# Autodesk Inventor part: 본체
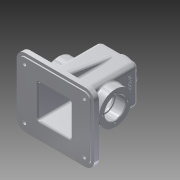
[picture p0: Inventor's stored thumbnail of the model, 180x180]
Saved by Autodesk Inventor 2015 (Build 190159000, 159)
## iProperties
Created: 2016-02
Part Number: 본체
Material: 알루미늄 6061
Document SubType Name: Modeling
Designer: Administrator
Density: 2.7 g/cm^3
Appearance: 알루미늄 - 평지
Mass: 797.447 g
Surface Area: 911.36 cm^2
Volume: 295.351 cm^3
Author: Administrator
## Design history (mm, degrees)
sketch "스케치1"
  geometry: L1 (65, 57.5)-(-65, 57.5); L2 (-65, 57.5)-(-65, -57.5); L3 (-65, -57.5)-(65, -57.5); L4 (65, -57.5)-(65, 57.5); L5 (65, 57.5)-(-65, -57.5); L6 (-65, 57.5)-(65, -57.5); 1 further point
  constraints: 12 end point, 2 midpoint, 2 parallel, 1 horizontal, 1 perpendicular
  dimensions: "d0" = 130 distance of L2.end L3.end; "d1" = 115 distance of L1.end L2.end
extrude "돌출1" new body sketch "스케치1" distance "d2" = 8; taper "d3" = 0 deg
sketch "스케치2"
  geometry: L1 (-60, 52.5)-(60, 52.5); L2 (60, 52.5)-(60, -52.5); L3 (60, -52.5)-(-60, -52.5); L4 (-60, -52.5)-(-60, 52.5); L5 (-60, 52.5)-(60, -52.5); L6 (60, 52.5)-(-60, -52.5); 1 further point
  constraints: 12 end point, 2 midpoint, 2 parallel, 1 horizontal, 1 perpendicular
  dimensions: "d4" = 120 distance of L2.end L3.end; "d5" = 105 distance of L1.end L2.end
extrude "돌출2" join sketch "스케치2" distance "d6" = 2; taper "d7" = 0 deg
sketch "스케치3"
  geometry: L1 (-65, -57.5)-(-65, 57.5) reference; L2 (-65, 57.5)-(65, 57.5) reference; L3 (65, 57.5)-(65, -57.5) reference; L4 (65, -57.5)-(-65, -57.5) reference; L5 (-32.5, -32.5)-(32.5, -32.5); L6 (32.5, -32.5)-(32.5, 32.5); L7 (32.5, 32.5)-(-32.5, 32.5); L8 (-32.5, 32.5)-(-32.5, -32.5); L9 (-32.5, -32.5)-(32.5, 32.5); L10 (32.5, -32.5)-(-32.5, 32.5); 1 further point
  constraints: 12 end point, 2 midpoint, 2 parallel, 1 horizontal, 1 perpendicular
  dimensions: "d8" = 65 distance of L6.end L7.end; "d9" = 65 distance of L5.end L6.end
extrude "돌출3" join sketch "스케치3" distance "d10" = 100; taper "d11" = 0 deg
sketch "스케치4"
  geometry: L1 (90, 0)-(90, -8) reference; L2 (90, -8)-(85, -8) reference; L3 (85, -8)-(85, -10) reference; L4 (85, -10)-(-20, -10) reference; L5 (-20, -10)-(-20, -8) reference; L6 (-20, -8)-(-25, -8) reference; L7 (-25, -8)-(-25, 0) reference; L8 (-25, 0)-(0, 0) reference; L9 (0, 0)-(65, 0) reference; L10 (65, 0)-(90, 0) reference; L11 (0, 0)-(0, 100) reference; L12 (0, 100)-(65, 100) reference; L13 (65, 100)-(65, 0) reference; L14 (-45.844, 45)-(144.35, 45); L15 (32.5, -8)-(32.5, 115.306); C1 r 27.5 at (32.5, 45)
  constraints: 4 end point, 2 point on line, 1 centre point, 1 horizontal, 1 vertical
  dimensions: "d12" = 55 distance between parallel lines of L4 L14; "d13" = 55 diameter of C1
extrude "돌출4" join sketch "스케치4" distance "d14" = 15; taper "d15" = 0 deg
sketch "스케치5"
  geometry: L1 (-25, -8)-(-25, 0) reference; L2 (-25, 0)-(0, 0) reference; L3 (0, 0)-(0, 100) reference; L4 (0, 100)-(65, 100) reference; L5 (65, 100)-(65, 0) reference; L6 (65, 0)-(90, 0) reference; L7 (90, 0)-(90, -8) reference; L8 (90, -8)-(85, -8) reference; L9 (85, -8)-(85, -10) reference; L10 (85, -10)-(-20, -10) reference; L11 (-20, -10)-(-20, -8) reference; L12 (-20, -8)-(-25, -8) reference; L13 (0, 0)-(65, 0) reference; L14 (-28.845, 45)-(133.756, 45); L15 (32.5, -8)-(32.5, 125.406); C1 r 27.5 at (32.5, 45)
  constraints: 4 end point, 2 point on line, 1 centre point, 1 horizontal, 1 vertical
  dimensions: "d16" = 55 distance between parallel lines of L10 L14; "d17" = 55 diameter of C1
extrude "돌출5" join sketch "스케치5" distance "d18" = 15; taper "d19" = 0 deg
sketch "스케치6"
  geometry: L1 (-32.5, -32.5)-(-32.5, 32.5) reference; L2 (-32.5, 32.5)-(32.5, 32.5) reference; L3 (32.5, 32.5)-(32.5, -32.5) reference; L4 (32.5, -32.5)-(-32.5, -32.5) reference; C1 r 20 at (0, 0); 1 further point
  constraints: 1 centre point, 1 coincident
  dimensions: "d21" = 40 diameter of C1
extrude "돌출6" join sketch "스케치6" distance "d22" = 10; taper "d23" = 0 deg
sketch "스케치7"
  geometry: C1 r 20 at (0, 0) reference; C2 r 10.5 at (0, 0); 1 further point
  constraints: 1 centre point, 1 coincident
  dimensions: "d24" = 21 diameter of C2
extrude "돌출7" cut sketch "스케치7" distance "d25" = 500; taper "d26" = 0 deg
sketch "스케치8" dims "d27" = 29
  geometry: C1 r 10.5 at (0, 0) reference; C2 r 20 at (0, 0) reference; 3 further points
  constraints: 2 vertical alignment, 1 coincident, 2 other
hole "구멍1" sketch "스케치8" at (0, 14.5) diameter "d28" = 2.459; stored, may be unused: countersink angle "d32" = 90 deg, drill point angle "d34" = 118 deg; dims "d29" = 7, "d30" = 4, "d31" = 2, "d33" = 9
sketch "스케치9"
  geometry: L1 (-27.5, -27.5)-(27.5, -27.5); L2 (27.5, -27.5)-(27.5, 27.5); L3 (27.5, 27.5)-(-27.5, 27.5); L4 (-27.5, 27.5)-(-27.5, -27.5); L5 (-27.5, -27.5)-(27.5, 27.5); L6 (27.5, -27.5)-(-27.5, 27.5); 1 further point
  constraints: 12 end point, 2 midpoint, 2 parallel, 1 horizontal, 1 perpendicular
  dimensions: "d38" = 55 distance of L2.end L3.end; "d39" = 55 distance of L1.end L2.end
extrude "돌출8" cut sketch "스케치9" distance "d40" = 105; taper "d41" = 0 deg
sketch "스케치10"
  geometry: L1 (57.5, -45)-(57.5, -53) reference; L2 (57.5, -53)-(52.5, -53) reference; L3 (52.5, -53)-(52.5, -55) reference; L4 (52.5, -55)-(-52.5, -55) reference; L5 (-52.5, -55)-(-52.5, -53) reference; L6 (-52.5, -53)-(-57.5, -53) reference; L7 (-57.5, -53)-(-57.5, -45) reference; L8 (-57.5, -45)-(57.5, -45) reference; C1 r 27.5 at (0, 0) reference; C2 r 17.5 at (0, 0); 1 further point
  constraints: 1 centre point, 1 coincident
  dimensions: "d42" = 35 diameter of C2
extrude "돌출9" cut sketch "스케치10" distance "d43" = 17; taper "d44" = 0 deg
sketch "스케치11"
  geometry: L1 (57.5, -45)-(57.5, -53) reference; L2 (57.5, -53)-(52.5, -53) reference; L3 (52.5, -53)-(52.5, -55) reference; L4 (52.5, -55)-(-52.5, -55) reference; L5 (-52.5, -55)-(-52.5, -53) reference; L6 (-52.5, -53)-(-57.5, -53) reference; L7 (-57.5, -53)-(-57.5, -45) reference; L8 (-57.5, -45)-(-32.5, -45) reference; L9 (-32.5, -45)-(-32.5, 55) reference; L10 (-32.5, 55)-(32.5, 55) reference; L11 (32.5, 55)-(32.5, -45) reference; L12 (32.5, -45)-(57.5, -45) reference; C1 r 17.5 at (0, 0) reference; C2 r 15 at (0, 0); 1 further point
  constraints: 1 centre point, 1 coincident
  dimensions: "d45" = 30 diameter of C2
extrude "돌출10" cut sketch "스케치11" distance "d46" = 3; taper "d47" = 0 deg
sketch "스케치12"
  geometry: L1 (-57.5, -53)-(-57.5, -45) reference; L2 (-57.5, -45)-(57.5, -45) reference; L3 (57.5, -45)-(57.5, -53) reference; L4 (57.5, -53)-(52.5, -53) reference; L5 (52.5, -53)-(52.5, -55) reference; L6 (52.5, -55)-(-52.5, -55) reference; L7 (-52.5, -55)-(-52.5, -53) reference; L8 (-52.5, -53)-(-57.5, -53) reference; C1 r 27.5 at (0, 0) reference; C2 r 17.5 at (0, 0); 1 further point
  constraints: 1 centre point, 1 coincident
  dimensions: "d48" = 35 diameter of C2
extrude "돌출11" cut sketch "스케치12" distance "d49" = 17; taper "d50" = 0 deg
sketch "스케치13"
  geometry: L1 (-57.5, -53)-(-57.5, -45) reference; L2 (-57.5, -45)-(-32.5, -45) reference; L3 (-32.5, -45)-(-32.5, 55) reference; L4 (-32.5, 55)-(32.5, 55) reference; L5 (32.5, 55)-(32.5, -45) reference; L6 (32.5, -45)-(57.5, -45) reference; L7 (57.5, -45)-(57.5, -53) reference; L8 (57.5, -53)-(52.5, -53) reference; L9 (52.5, -53)-(52.5, -55) reference; L10 (52.5, -55)-(-52.5, -55) reference; L11 (-52.5, -55)-(-52.5, -53) reference; L12 (-52.5, -53)-(-57.5, -53) reference; C1 r 17.5 at (0, 0) reference; C2 r 15 at (0, 0); 1 further point
  constraints: 1 centre point, 1 coincident
  dimensions: "d51" = 30 diameter of C2
extrude "돌출12" cut sketch "스케치13" distance "d52" = 3; taper "d53" = 0 deg
sketch "스케치14" dims "d54" = 42
  geometry: L1 (-57.5, -53)-(-57.5, -45) reference; L2 (-57.5, -45)-(57.5, -45) reference; L3 (57.5, -45)-(57.5, -53) reference; L4 (57.5, -53)-(52.5, -53) reference; L5 (52.5, -53)-(52.5, -55) reference; L6 (52.5, -55)-(-52.5, -55) reference; L7 (-52.5, -55)-(-52.5, -53) reference; L8 (-52.5, -53)-(-57.5, -53) reference; C1 r 17.5 at (0, 0) reference; C2 r 27.5 at (0, 0) reference; 3 further points
  constraints: 2 vertical alignment, 1 coincident, 2 other
hole "구멍2" sketch "스케치14" at (0, 21) diameter "d55" = 3.242; stored, may be unused: countersink angle "d59" = 90 deg, drill point angle "d61" = 118 deg; dims "d56" = 8, "d57" = 4, "d58" = 2, "d60" = 10
sketch "스케치15" dims "d65" = 42
  geometry: L1 (57.5, -45)-(57.5, -53) reference; L2 (57.5, -53)-(52.5, -53) reference; L3 (52.5, -53)-(52.5, -55) reference; L4 (52.5, -55)-(-52.5, -55) reference; L5 (-52.5, -55)-(-52.5, -53) reference; L6 (-52.5, -53)-(-57.5, -53) reference; L7 (-57.5, -53)-(-57.5, -45) reference; L8 (-57.5, -45)-(57.5, -45) reference; C1 r 17.5 at (0, 0) reference; C2 r 27.5 at (0, 0) reference; 3 further points
  constraints: 2 vertical alignment, 1 coincident, 2 other
hole "구멍3" sketch "스케치15" at (0, 21) diameter "d66" = 3.242; stored, may be unused: countersink angle "d70" = 90 deg, drill point angle "d72" = 118 deg; dims "d67" = 8, "d68" = 4, "d69" = 2, "d71" = 10
fillet "모깎기1" dims "d76" = 10
sketch "스케치17"
  geometry: L1 (-50, 52.5)-(50, 52.5) reference; L2 (60, 42.5)-(60, -42.5) reference; L3 (50, -52.5)-(-50, -52.5) reference; L4 (-60, -42.5)-(-60, 42.5) reference; L5 (27.5, -27.5)-(27.5, 27.5) reference; L6 (27.5, 27.5)-(-27.5, 27.5) reference; L7 (-27.5, 27.5)-(-27.5, -27.5) reference; L8 (-27.5, -27.5)-(27.5, -27.5) reference; C1 r 3 at (50, -42.5); C2 r 3 at (-50, -42.5); C3 r 3 at (-50, 42.5); C4 r 3 at (50, 42.5); A1 r 10 centre (-50, 42.5) between (-50, 52.5) and (-60, 42.5) reference; A2 r 10 centre (50, 42.5) between (60, 42.5) and (50, 52.5) reference; A3 r 10 centre (50, -42.5) between (50, -52.5) and (60, -42.5) reference; A4 r 10 centre (-50, -42.5) between (-60, -42.5) and (-50, -52.5) reference; 1 further point
  constraints: 4 centre point, 4 coincident
  dimensions: "d77" = 6 diameter of C1; "d79" = 6 diameter of C2; "d80" = 6 diameter of C3; "d81" = 6 diameter of C4
extrude "돌출13" cut sketch "스케치17" distance "d82" = 30; taper "d83" = 0 deg
sketch "스케치19"
  geometry: L1 (27.5, -27.5)-(27.5, 27.5) reference; L2 (27.5, 27.5)-(-27.5, 27.5) reference; L3 (-27.5, 27.5)-(-27.5, -27.5) reference; L4 (-27.5, -27.5)-(27.5, -27.5) reference; L5 (-32.5, -32.5)-(-32.5, 32.5) reference; L6 (-32.5, 32.5)-(32.5, 32.5) reference; L7 (32.5, 32.5)-(32.5, -32.5) reference; L8 (32.5, -32.5)-(-32.5, -32.5) reference; L9 (-65, -57.5)-(-65, 57.5) reference; L10 (-65, 57.5)-(65, 57.5) reference; L11 (65, 57.5)-(65, -57.5) reference; L12 (65, -57.5)-(-65, -57.5) reference; C1 r 3 at (-50, -42.5) reference; C2 r 3 at (50, 42.5) reference; C3 r 3 at (-50, 42.5) reference; C4 r 3 at (50, -42.5) reference; C5 r 7.5 at (50, -42.5); C6 r 7.5 at (-50, -42.5); C7 r 7.5 at (-50, 42.5); C8 r 7.5 at (50, 42.5); 1 further point
  constraints: 4 centre point, 4 coincident, 3 equal radius
  dimensions: "d84" = 15 diameter of C5
extrude "돌출14" join sketch "스케치19" distance "d85" = 3; taper "d86" = 0 deg
sketch "스케치20"
  geometry: L1 (-22.5, 15)-(-22.5, 70) reference; L2 (-22.5, 70)-(-77.5, 70) reference; L3 (-77.5, 70)-(-77.5, 15) reference; L4 (-77.5, 15)-(-22.5, 15) reference; L5 (-82.5, 10)-(-82.5, 75) reference; L6 (-82.5, 75)-(-17.5, 75) reference; L7 (-17.5, 75)-(-17.5, 10) reference; L8 (-17.5, 10)-(-82.5, 10) reference; C1 r 7.5 at (-100, 85) reference; C2 r 7.5 at (0, 0) reference; C3 r 7.5 at (-100, 0) reference; C4 r 7.5 at (0, 85) reference; C5 r 3 at (0, 0); C6 r 3 at (-100, 0); C7 r 3 at (-100, 85); C8 r 3 at (0, 85); 1 further point
  constraints: 4 centre point, 4 coincident
  dimensions: "d87" = 6 diameter of C6; "d88" = 6 diameter of C7; "d89" = 6 diameter of C8; "d90" = 6 diameter of C5
extrude "돌출15" cut sketch "스케치20" distance "d91" = 3; taper "d92" = 0 deg
sketch "스케치21"
  geometry: L1 (8, -57.5)-(0, -57.5) reference; L2 (0, -57.5)-(0, -52.5) reference; L3 (0, -52.5)-(-2, -52.5) reference; L4 (-2, -52.5)-(-2, -27.5) reference; L5 (-2, -27.5)-(103, -27.5) reference; L6 (103, -27.5)-(103, -10.5) reference; L7 (103, -10.5)-(118, -10.5) reference; L8 (118, -10.5)-(118, -13.271) reference; L9 (118, -13.271)-(109, -13.271) reference; L10 (109, -13.271)-(108.261, -14.5) reference; L11 (108.261, -14.5)-(109, -15.73) reference; L12 (109, -15.73)-(118, -15.73) reference; L13 (118, -15.73)-(118, -20) reference; L14 (118, -20)-(108, -20) reference; L15 (108, -20)-(108, -32.5) reference; L16 (108, -32.5)-(8, -32.5) reference; L17 (8, -32.5)-(8, -57.5) reference; L18 (0, 57.5)-(8, 57.5) reference; L19 (8, 57.5)-(8, 32.5) reference; L20 (8, 32.5)-(108, 32.5) reference; L21 (108, 32.5)-(108, 20) reference; L22 (108, 20)-(118, 20) reference; L23 (118, 20)-(118, 15.73) reference; L24 (118, 15.73)-(109, 15.73) reference; L25 (109, 15.73)-(108.261, 14.5) reference; L26 (108.261, 14.5)-(109, 13.271) reference; L27 (109, 13.271)-(118, 13.271) reference; L28 (118, 13.271)-(118, 10.5) reference; L29 (118, 10.5)-(103, 10.5) reference; L30 (103, 10.5)-(103, 27.5) reference; L31 (103, 27.5)-(-2, 27.5) reference; L32 (-2, 27.5)-(-2, 52.5) reference; L33 (-2, 52.5)-(0, 52.5) reference; L34 (0, 52.5)-(0, 57.5) reference; L35 (8, 32.5)-(108, 32.5) reference; L36 (93.069, 32.5)-(8, 47.5); L37 (8, -57.5)-(8, 57.5) reference; L38 (8, 32.5)-(93.069, 32.5); L39 (8, 32.5)-(8, 47.5); 1 further point
  constraints: 6 end point, 2 point on line, 1 collinear, 1 vertical
  dimensions: "d95" = 10 deg angle of L36 L18; "d96" = 10 distance of L18.end L36.end
extrude "돌출16" join sketch "스케치21" stored distance "d97" = 10; taper "d98" = 0 deg
sketch "스케치22"
  geometry: L1 (108, 20)-(118, 20) reference; L2 (118, 20)-(118, 15.73) reference; L3 (118, 15.73)-(109, 15.73) reference; L4 (109, 15.73)-(108.261, 14.5) reference; L5 (108.261, 14.5)-(109, 13.271) reference; L6 (109, 13.271)-(118, 13.271) reference; L7 (118, 13.271)-(118, 10.5) reference; L8 (118, 10.5)-(103, 10.5) reference; L9 (103, 10.5)-(103, 27.5) reference; L10 (103, 27.5)-(-2, 27.5) reference; L11 (-2, 27.5)-(-2, 52.5) reference; L12 (-2, 52.5)-(0, 52.5) reference; L13 (0, 52.5)-(0, 57.5) reference; L14 (0, 57.5)-(8, 57.5) reference; L15 (8, 57.5)-(8, 47.5) reference; L16 (8, 47.5)-(93.069, 32.5) reference; L17 (93.069, 32.5)-(108, 32.5) reference; L18 (108, 32.5)-(108, 20) reference; L19 (118, -20)-(108, -20) reference; L20 (108, -20)-(108, -32.5) reference; L21 (108, -32.5)-(8, -32.5) reference; L22 (8, -32.5)-(8, -57.5) reference; L23 (8, -57.5)-(0, -57.5) reference; L24 (0, -57.5)-(0, -52.5) reference; L25 (0, -52.5)-(-2, -52.5) reference; L26 (-2, -52.5)-(-2, -27.5) reference; L27 (-2, -27.5)-(103, -27.5) reference; L28 (103, -27.5)-(103, -10.5) reference; L29 (103, -10.5)-(118, -10.5) reference; L30 (118, -10.5)-(118, -13.271) reference; L31 (118, -13.271)-(109, -13.271) reference; L32 (109, -13.271)-(108.261, -14.5) reference; L33 (108.261, -14.5)-(109, -15.73) reference; L34 (109, -15.73)-(118, -15.73) reference; L35 (118, -15.73)-(118, -20) reference; L36 (8, -32.5)-(108, -32.5) reference; L37 (93.069, -32.5)-(8, -47.5); L38 (8, -32.5)-(93.069, -32.5); L39 (8, -35)-(8, -50) reference; L40 (8, -32.5)-(8, -47.5); 1 further point
  constraints: 6 end point, 2 point on line, 1 perpendicular, 1 vertical
  dimensions: "d99" = 10 distance of L22.end L37.end; "d100" = 10 deg angle of L23 L37
extrude "돌출17" join sketch "스케치22" stored distance "d101" = 10; taper "d102" = 0 deg
sketch "스케치24"
  geometry: L1 (-20, -10)-(-20, -8) reference; L2 (-20, -8)-(-25, -8) reference; L3 (-25, -8)-(-25, 0) reference; L4 (-25, 0)-(0, 0) reference; L5 (0, 0)-(65, 0) reference; L6 (65, 100)-(65, 0) reference; L7 (0, 100)-(65, 100) reference; L8 (0, 0)-(0, 100) reference; L9 (85, -10)-(-20, -10) reference; L10 (85, -8)-(85, -10) reference; L11 (90, -8)-(85, -8) reference; L12 (90, 0)-(90, -8) reference; L13 (65, 0)-(90, 0) reference; L14 (52.5, 110)-(12.5, 110) reference; C1 r 17.5 at (32.5, 45) reference; C2 r 27.5 at (32.5, 45) reference; 2 further points
  constraints: 1 other
  dimensions: "d103" = 26 distance from line of point (32.5, 84) L14; "d104" = 32.5 distance from line of point (32.5, 84) L8
feature "엠보싱1" sketch "스케치24" dims "d105" = 0.5, "d106" = 0
fillet "모깎기2" dims "d107" = 15
fillet "모깎기4" dims "d109" = 3
fillet "모깎기6" dims "d111" = 8
fillet "모깎기7" dims "d112" = 8
fillet "모깎기10" dims "d115" = 3
fillet "모깎기11" dims "d116" = 3
fillet "모깎기12" dims "d117" = 3
fillet "모깎기13" dims "d118" = 3
fillet "모깎기14" dims "d119" = 0.3
chamfer "모따기1" distance "d120" = 1; stored, may be unused: second distance "d121" = 2, angle "d122" = 45 deg
chamfer "모따기2" distance "d123" = 1; stored, may be unused: second distance "d124" = 2, angle "d125" = 45 deg
fillet "모깎기15" dims "d126" = 3
sketch "스케치26"
  geometry: L1 (0, 92)-(49, 92) reference; L2 (49, 57.49)-(49, 92) reference; L3 (0, 0)-(0, 32.51) reference; L4 (-33, 0)-(0, 0) reference; L5 (-33, -8)-(-33, 0) reference; L6 (-28, -8)-(-33, -8) reference; L7 (-28, -10)-(-28, -8) reference; L8 (77, -10)-(-28, -10) reference; L9 (77, -8)-(77, -10) reference; L10 (82, -8)-(77, -8) reference; L11 (82, 0)-(82, -8) reference; L12 (49, 0)-(82, 0) reference; L13 (0, 0)-(49, 0) reference; L14 (0, 57.49)-(0, 92) reference; L15 (49, 0)-(49, 32.51) reference; L16 (43.489, 83.997)-(42.159, 83.997) reference; L17 (42.159, 83.997)-(42.159, 84.377) reference; L18 (42.159, 84.377)-(43.489, 84.377) reference; L19 (43.489, 84.377)-(43.489, 86.955) reference; L20 (43.489, 86.955)-(43.815, 86.955) reference; L21 (43.95, 86.69)-(43.95, 81.018) reference; L22 (43.95, 81.018)-(43.489, 81.018) reference; L23 (43.489, 81.018)-(43.489, 83.997) reference; L24 (10.558, 84.648)-(10.558, 84.254) reference; L25 (10.558, 84.254)-(9.439, 84.254) reference; L26 (9.439, 84.254)-(9.439, 82.511) reference; L27 (9.439, 82.511)-(8.964, 82.511) reference; L28 (8.964, 82.511)-(8.964, 87.002) reference; L29 (8.964, 87.002)-(9.269, 87.002) reference; L30 (9.439, 86.737)-(9.439, 84.648) reference; L31 (9.439, 84.648)-(10.558, 84.648) reference; L32 (9.656, 81.561)-(9.656, 81.181) reference; L33 (9.656, 81.181)-(5.307, 81.181) reference; L34 (5.307, 81.181)-(5.307, 82.809) reference; L35 (5.307, 82.809)-(5.66, 82.809) reference; L36 (5.769, 82.592)-(5.769, 81.561) reference; L37 (5.769, 81.561)-(9.656, 81.561) reference; L38 (7.126, 86.425)-(5.647, 86.425) reference; L39 (5.647, 86.425)-(5.647, 86.778) reference; L40 (5.647, 86.778)-(7.126, 86.778) reference; L41 (7.126, 86.778)-(7.126, 86.425) reference; L42 (4.453, 85.618)-(4.453, 85.971) reference; L43 (4.453, 85.971)-(8.218, 85.971) reference; L44 (8.218, 85.971)-(8.218, 85.618) reference; L45 (8.218, 85.618)-(4.453, 85.618) reference; L46 (21.583, 81.385)-(21.026, 82.911) reference; L47 (21.026, 82.911)-(18.774, 82.911) reference; L48 (18.774, 82.911)-(18.204, 81.385) reference; L49 (18.204, 81.385)-(17.723, 81.385) reference; L50 (17.723, 81.385)-(19.622, 86.385) reference; L51 (19.622, 86.385)-(20.165, 86.385) reference; L52 (20.165, 86.385)-(22.064, 81.385) reference; L53 (22.064, 81.385)-(21.583, 81.385) reference; L54 (19.887, 85.896)-(18.93, 83.325) reference; L55 (18.93, 83.325)-(20.864, 83.325) reference; L56 (20.864, 83.325)-(19.887, 85.896) reference; L57 (14.405, 83.149)-(16.216, 83.149) reference; L58 (16.216, 83.149)-(16.216, 81.025) reference; L59 (16.216, 81.025)-(15.755, 81.025) reference; L60 (15.755, 81.025)-(15.755, 82.775) reference; L61 (15.755, 82.775)-(11.922, 82.775) reference; L62 (11.922, 82.775)-(11.922, 83.149) reference; L63 (11.922, 83.149)-(13.95, 83.149) reference; L64 (13.95, 83.149)-(13.95, 84.37) reference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; C1 r 17.5 at (24.5, 45) reference; A1 r 27.5 centre (24.5, 45) between (49, 57.49) and (0, 57.49) reference; A2 r 27.5 centre (24.5, 45) between (0, 57.49) and (0, 32.51) reference; A3 r 27.5 centre (24.5, 45) between (49, 32.51) and (49, 57.49) reference; A4 r 27.5 centre (24.5, 45) between (0, 32.51) and (49, 32.51) reference; 64 further points
  constraints: 12 end point, 3 midpoint, 2 parallel, 1 collinear, 1 horizontal, 1 perpendicular, 1 vertical alignment, 76 other
  dimensions: "d127" = 20 distance of L116.end L117.end; "d128" = 4.41041 distance of L116.start L116.end
extrude "돌출18" join sketch "스케치26" distance "d129" = 10; taper "d130" = 0 deg
sketch "스케치27"
  geometry: L1 (0, 92)-(49, 92) reference; L2 (49, 57.49)-(49, 92) reference; L3 (0, 0)-(0, 32.51) reference; L4 (-33, 0)-(0, 0) reference; L5 (-33, -8)-(-33, 0) reference; L6 (-28, -8)-(-33, -8) reference; L7 (-28, -10)-(-28, -8) reference; L8 (77, -10)-(-28, -10) reference; L9 (77, -8)-(77, -10) reference; L10 (82, -8)-(77, -8) reference; L11 (82, 0)-(82, -8) reference; L12 (49, 0)-(82, 0) reference; L13 (0, 0)-(49, 0) reference; L14 (0, 57.49)-(0, 92) reference; L15 (49, 0)-(49, 32.51) reference; L16 (21.5, 20)-(27.5, 20); L17 (27.5, 20)-(27.5, 0); L18 (27.5, 0)-(21.5, 0); L19 (21.5, 0)-(21.5, 20); L20 (21.5, 20)-(27.5, 0); L21 (27.5, 20)-(21.5, 0); C1 r 17.5 at (24.5, 45) reference; A1 r 27.5 centre (24.5, 45) between (49, 57.49) and (0, 57.49) reference; A2 r 27.5 centre (24.5, 45) between (0, 57.49) and (0, 32.51) reference; A3 r 27.5 centre (24.5, 45) between (49, 32.51) and (49, 57.49) reference; A4 r 27.5 centre (24.5, 45) between (0, 32.51) and (49, 32.51) reference; 3 further points
  constraints: 12 end point, 3 midpoint, 2 parallel, 1 collinear, 1 horizontal, 1 perpendicular, 1 vertical alignment
  dimensions: "d131" = 20 distance of L16.end L17.end; "d132" = 6 distance of L17.end L18.end
extrude "돌출19" join sketch "스케치27" distance "d133" = 10; taper "d134" = 0 deg
fillet "모깎기16" dims "d135" = 3
fillet "모깎기17" dims "d136" = 1
fillet "모깎기18" dims "d137" = 3
chamfer "모따기3" distance "d138" = 1; stored, may be unused: second distance "d139" = 2, angle "d140" = 45 deg
node "솔리드1"
pattern_circular "원형 패턴1" dims angle "d36" = 360 deg
pattern_circular "원형 패턴2" dims angle "d63" = 360 deg
pattern_circular "원형 패턴3" dims angle "d74" = 360 deg
node "절단 모서리 투영1"
node "절단 모서리 투영2"
node "절단 모서리 투영3"
node "절단 모서리 투영4"
node "절단 모서리 투영5"
node "절단 모서리 투영6"
node "절단 모서리 투영7"
node "절단 모서리 투영8"
node "절단 모서리 투영9"
node "절단 모서리 투영10"
node "절단 모서리 투영11"
node "절단 모서리 투영12"
node "절단 모서리 투영14"
node "절단 모서리 투영15"
node "절단 모서리 투영16"
node "절단 모서리 투영17"
node "절단 모서리 투영18"
node "절단 모서리 투영20"
node "절단 모서리 투영22"
node "절단 모서리 투영23"
